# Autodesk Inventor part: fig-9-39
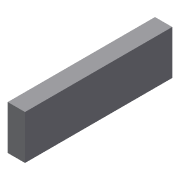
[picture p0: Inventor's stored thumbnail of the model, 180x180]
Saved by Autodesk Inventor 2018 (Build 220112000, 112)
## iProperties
Created: 2013-03
Part Number: fig-9-39
Material: Generic
Document SubType Name: Modeling
Designer: CADCIM
Density: 1 g/cm^3
Appearance: Default
Author: CADCIM
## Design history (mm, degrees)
sketch "Sketch1"
  geometry: L1 (-11.87, 2.655)-(7.31, 2.655); L2 (7.31, 2.655)-(7.31, -3.093); L3 (7.31, -3.093)-(-11.87, -3.093); L4 (-11.87, -3.093)-(-11.87, 2.655); 1 further point
  constraints: 8 end point, 2 parallel, 1 horizontal, 1 perpendicular
extrude "Extrusion1" new body sketch "Sketch1" distance "d0" = 2.25; taper "d1" = 0 deg
body "Solid1"
